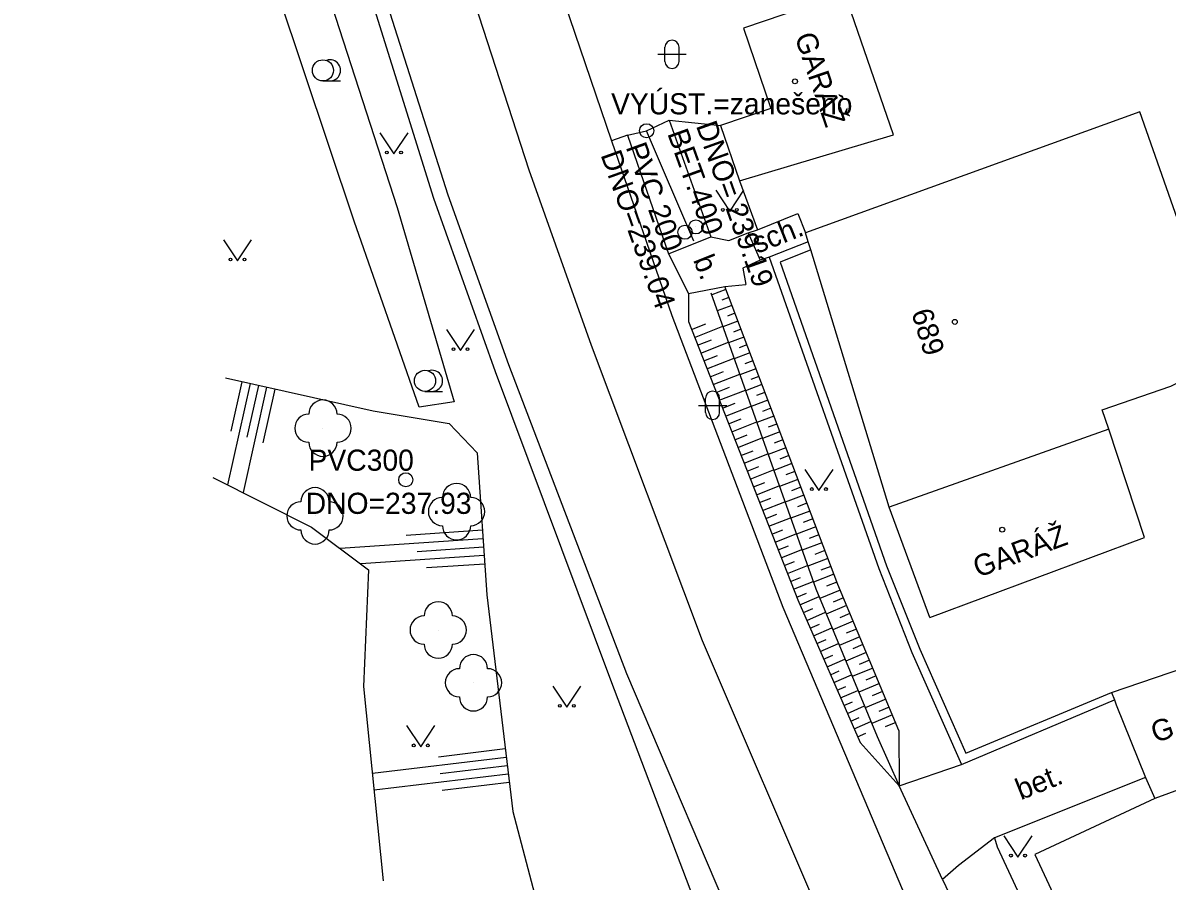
# Model space of a CAD drawing. Extents: x -621335 to -621199, y -1175437 to -1175180.
# Drawn here: x -621302.63 to -621262.05, y -1175367.71 to -1175337.27 of the extents above; entities that cross this region are included whole.
import ezdxf

# ---------------------------------------------------------------- set-up
doc = ezdxf.new("R2010")
doc.units = 0
for name, color, linetype in [('Budovy - měřené', 7, 'Continuous'), ('Budovy - zadní trakty', 7, 'Continuous'), ('Doplňkové značky', 7, 'Continuous'), ('Pomocné popisy', 7, 'Continuous'), ('Rozhraní ploch', 7, 'Continuous'), ('Výškopis', 7, 'Continuous'), ('Zeleň', 7, 'Continuous'), ('Značky druhů budov', 7, 'Continuous'), ('Značky kultur', 7, 'Continuous'), ('Čísla popisná_evidenční', 7, 'Continuous')]:
    doc.layers.add(name, color=color, linetype=linetype)

msp = doc.modelspace()

# ---------------------------------------------------------------- linework, layer by layer
at = {"layer": 'Budovy - měřené'}
msp.add_line((-621262.82, -1175364.04), (-621262.49, -1175364.79), dxfattribs=at)
for points in [[(-621277.08, -1175337.46), (-621276.1, -1175340.31), (-621277.89, -1175340.92), (-621277.22, -1175342.88)], [(-621270.47, -1175358.36), (-621271.91, -1175354.45), (-621274.69, -1175345.33), (-621274.78, -1175345.04), (-621274.88, -1175344.72)], [(-621264.02, -1175361.02), (-621263.92, -1175361.29), (-621263.86, -1175361.46)], [(-621262.49, -1175364.79), (-621266.74, -1175366.77), (-621264.62, -1175371.33)]]:
    msp.add_lwpolyline(points, dxfattribs=at)
at = {"layer": 'Budovy - zadní trakty'}
for points in [[(-621277.22, -1175342.88), (-621271.76, -1175341.24), (-621273.48, -1175336.23), (-621277.08, -1175337.46)], [(-621264.12, -1175351.69), (-621264.35, -1175351), (-621261.92, -1175350.16), (-621259.94, -1175349.19), (-621263.02, -1175340.43), (-621274.88, -1175344.72)], [(-621270.47, -1175358.36), (-621262.85, -1175355.53), (-621264.12, -1175351.69), (-621271.91, -1175354.45)], [(-621264.02, -1175361.02), (-621258.82, -1175359.25), (-621257.55, -1175362.98), (-621262.49, -1175364.79)]]:
    msp.add_lwpolyline(points, dxfattribs=at)
at = {"layer": 'Doplňkové značky'}
for p, q in [((-621277.22, -1175342.88), (-621276.58, -1175344.61)), ((-621275.15, -1175344.04), (-621274.88, -1175344.72)), ((-621276.91, -1175344.72), (-621276.48, -1175345.69)), ((-621263.86, -1175361.46), (-621262.82, -1175364.04))]:
    msp.add_line(p, q, dxfattribs=at)
for points in [[(-621277.59, -1175344.99), (-621276.91, -1175344.72), (-621276.58, -1175344.61), (-621275.15, -1175344.04)], [(-621274.78, -1175345.04), (-621276.16, -1175345.59), (-621272.28, -1175356.63), (-621271.1, -1175359.61), (-621269.34, -1175363.58), (-621263.92, -1175361.29)], [(-621274.69, -1175345.33), (-621275.78, -1175345.76), (-621272, -1175356.53), (-621270.82, -1175359.49), (-621269.19, -1175363.18), (-621264.02, -1175361.02)], [(-621276.16, -1175345.59), (-621276.48, -1175345.69), (-621277.1, -1175345.97), (-621276.99, -1175346.56)], [(-621262.82, -1175364.04), (-621268.17, -1175366.18), (-621269.45, -1175367.16)]]:
    msp.add_lwpolyline(points, dxfattribs=at)
for centre, radius in [((-621280.51, -1175341.1), 0.25), ((-621280.51, -1175341.1), 0.0005), ((-621279.15, -1175344.7), 0.25), ((-621278.76, -1175344.51), 0.25), ((-621278.76, -1175344.51), 0.0005), ((-621279.15, -1175344.7), 0.0005), ((-621289.051, -1175353.48), 0.25), ((-621289.051, -1175353.48), 0.0005)]:
    msp.add_circle(centre, radius, dxfattribs=at)
at = {"layer": 'Rozhraní ploch'}
for p, q in [((-621279.73, -1175345.47), (-621278.23, -1175344.86)), ((-621278.23, -1175344.86), (-621277.59, -1175344.99)), ((-621279.73, -1175345.47), (-621279.02, -1175346.87)), ((-621279.02, -1175346.87), (-621277.74, -1175346.63)), ((-621277.74, -1175346.63), (-621276.99, -1175346.56)), ((-621271.55, -1175364.33), (-621269.34, -1175363.58)), ((-621270.02, -1175367.66), (-621271.55, -1175364.33)), ((-621269.45, -1175367.16), (-621270.02, -1175367.66))]:
    msp.add_line(p, q, dxfattribs=at)
for points in [[(-621302.63, -1175296.18), (-621299, -1175307.51), (-621296.71, -1175314.71), (-621292.18, -1175328.86), (-621287.56, -1175343.37)], [(-621287.87, -1175322.58), (-621286.35, -1175327.4), (-621283.25, -1175337.09), (-621281.75, -1175341.46), (-621279.62, -1175347.65), (-621275.68, -1175358)], [(-621289.26, -1175328.38), (-621284.69, -1175342.49), (-621282.48, -1175348.71), (-621278.54, -1175359.18), (-621274.2, -1175369.3), (-621270.32, -1175376.95), (-621266.97, -1175382.2), (-621259.66, -1175391.26), (-621249.09, -1175401.63), (-621240, -1175407.99), (-621230.92, -1175409.11)], [(-621287.56, -1175343.37), (-621285.41, -1175349.39), (-621281.22, -1175360.35)], [(-621275.68, -1175358), (-621271.3, -1175368.33), (-621268.96, -1175373.16)], [(-621281.22, -1175360.35), (-621276.93, -1175370.43), (-621272.83, -1175378.46)]]:
    msp.add_lwpolyline(points, dxfattribs=at)
at = {"layer": 'Výškopis'}
for p, q in [((-621279.71, -1175340.73), (-621278.23, -1175344.86)), ((-621281.19, -1175341.26), (-621279.73, -1175345.47)), ((-621278.84, -1175345.02), (-621280.51, -1175341.1)), ((-621279.02, -1175346.87), (-621279.03, -1175347.87)), ((-621277.7, -1175346.735), (-621278.203, -1175346.926)), ((-621277.487, -1175347.296), (-621278.003, -1175347.491)), ((-621277.594, -1175347.015), (-621277.848, -1175347.112)), ((-621277.381, -1175347.576), (-621277.642, -1175347.675)), ((-621278.92, -1175348.149), (-621278.415, -1175347.951)), ((-621278.81, -1175348.428), (-621277.81, -1175348.035)), ((-621277.275, -1175347.857), (-621277.802, -1175348.057)), ((-621277.168, -1175348.137), (-621277.435, -1175348.239)), ((-621278.701, -1175348.708), (-621278.205, -1175348.513)), ((-621277.062, -1175348.418), (-621277.602, -1175348.623)), ((-621278.591, -1175348.987), (-621277.61, -1175348.601)), ((-621276.849, -1175348.979), (-621277.402, -1175349.188)), ((-621276.955, -1175348.698), (-621277.229, -1175348.802)), ((-621278.481, -1175349.266), (-621277.995, -1175349.075)), ((-621278.371, -1175349.545), (-621277.409, -1175349.167)), ((-621276.743, -1175349.259), (-621277.022, -1175349.365)), ((-621278.262, -1175349.824), (-621277.785, -1175349.637)), ((-621278.152, -1175350.104), (-621277.209, -1175349.733)), ((-621276.636, -1175349.54), (-621277.201, -1175349.754)), ((-621294.572, -1175350.066), (-621295.374, -1175353.659)), ((-621294.864, -1175350.001), (-621295.257, -1175351.761)), ((-621293.986, -1175350.197), (-621294.821, -1175353.937)), ((-621294.279, -1175350.131), (-621294.688, -1175351.965)), ((-621278.042, -1175350.383), (-621277.575, -1175350.199)), ((-621276.423, -1175350.101), (-621277.001, -1175350.32)), ((-621276.53, -1175349.82), (-621276.815, -1175349.929)), ((-621293.693, -1175350.262), (-621294.119, -1175352.169)), ((-621277.932, -1175350.662), (-621277.008, -1175350.299)), ((-621276.317, -1175350.381), (-621276.609, -1175350.492)), ((-621277.823, -1175350.941), (-621277.365, -1175350.761)), ((-621277.713, -1175351.22), (-621276.808, -1175350.865)), ((-621276.21, -1175350.662), (-621276.8, -1175350.885)), ((-621276.104, -1175350.942), (-621276.402, -1175351.055)), ((-621277.603, -1175351.5), (-621277.155, -1175351.324)), ((-621275.998, -1175351.223), (-621276.6, -1175351.451)), ((-621277.493, -1175351.779), (-621276.607, -1175351.43)), ((-621275.785, -1175351.784), (-621276.399, -1175352.017)), ((-621275.891, -1175351.503), (-621276.195, -1175351.619)), ((-621277.384, -1175352.058), (-621276.945, -1175351.886)), ((-621277.274, -1175352.337), (-621276.407, -1175351.996)), ((-621275.678, -1175352.064), (-621275.989, -1175352.182)), ((-621277.164, -1175352.616), (-621276.735, -1175352.448)), ((-621277.054, -1175352.896), (-621276.206, -1175352.562)), ((-621275.572, -1175352.345), (-621276.199, -1175352.582)), ((-621275.466, -1175352.625), (-621275.782, -1175352.745)), ((-621276.945, -1175353.175), (-621276.525, -1175353.01)), ((-621275.359, -1175352.906), (-621275.999, -1175353.148)), ((-621276.835, -1175353.454), (-621276.006, -1175353.128)), ((-621275.253, -1175353.186), (-621275.576, -1175353.309)), ((-621276.725, -1175353.733), (-621276.315, -1175353.572)), ((-621276.615, -1175354.012), (-621275.805, -1175353.694)), ((-621275.146, -1175353.467), (-621275.798, -1175353.714)), ((-621275.04, -1175353.747), (-621275.369, -1175353.872)), ((-621276.506, -1175354.292), (-621276.105, -1175354.134)), ((-621276.396, -1175354.571), (-621275.605, -1175354.26)), ((-621274.934, -1175354.028), (-621275.598, -1175354.28)), ((-621274.721, -1175354.589), (-621275.397, -1175354.845)), ((-621274.827, -1175354.308), (-621275.162, -1175354.435)), ((-621276.286, -1175354.85), (-621275.895, -1175354.696)), ((-621276.176, -1175355.129), (-621275.404, -1175354.826)), ((-621274.614, -1175354.869), (-621274.956, -1175354.999)), ((-621286.334, -1175355.273), (-621289.042, -1175355.456)), ((-621276.067, -1175355.408), (-621275.685, -1175355.259)), ((-621275.957, -1175355.688), (-621275.204, -1175355.392)), ((-621274.508, -1175355.15), (-621275.197, -1175355.411)), ((-621274.401, -1175355.43), (-621274.749, -1175355.562)), ((-621286.314, -1175355.573), (-621291.381, -1175355.914)), ((-621286.294, -1175355.872), (-621288.653, -1175356.031)), ((-621275.847, -1175355.967), (-621275.475, -1175355.821)), ((-621274.295, -1175355.711), (-621274.997, -1175355.977)), ((-621286.274, -1175356.171), (-621290.643, -1175356.466)), ((-621275.737, -1175356.246), (-621275.003, -1175355.958)), ((-621274.082, -1175356.272), (-621274.796, -1175356.542)), ((-621274.189, -1175355.991), (-621274.543, -1175356.125)), ((-621286.253, -1175356.471), (-621288.313, -1175356.609)), ((-621275.628, -1175356.525), (-621275.265, -1175356.383)), ((-621275.518, -1175356.804), (-621274.803, -1175356.523)), ((-621273.976, -1175356.552), (-621274.336, -1175356.689)), ((-621275.408, -1175357.084), (-621275.055, -1175356.945)), ((-621275.298, -1175357.363), (-621274.602, -1175357.089)), ((-621273.869, -1175356.832), (-621274.596, -1175357.108)), ((-621275.189, -1175357.642), (-621274.845, -1175357.507)), ((-621273.65, -1175357.391), (-621274.368, -1175357.692)), ((-621273.763, -1175357.113), (-621274.128, -1175357.252)), ((-621275.072, -1175357.918), (-621274.397, -1175357.623)), ((-621273.534, -1175357.667), (-621273.893, -1175357.818)), ((-621274.952, -1175358.193), (-621274.617, -1175358.047)), ((-621274.832, -1175358.468), (-621274.167, -1175358.178)), ((-621273.418, -1175357.944), (-621274.138, -1175358.246)), ((-621273.302, -1175358.221), (-621273.662, -1175358.372)), ((-621274.712, -1175358.743), (-621274.382, -1175358.599)), ((-621273.185, -1175358.497), (-621273.908, -1175358.801)), ((-621274.592, -1175359.018), (-621273.937, -1175358.732)), ((-621272.953, -1175359.051), (-621273.678, -1175359.355)), ((-621273.069, -1175358.774), (-621273.431, -1175358.926)), ((-621274.472, -1175359.293), (-621274.147, -1175359.151)), ((-621274.352, -1175359.568), (-621273.707, -1175359.286)), ((-621272.837, -1175359.327), (-621273.2, -1175359.48)), ((-621274.232, -1175359.843), (-621273.912, -1175359.703)), ((-621274.111, -1175360.118), (-621273.477, -1175359.841)), ((-621272.721, -1175359.604), (-621273.448, -1175359.909)), ((-621272.605, -1175359.88), (-621272.969, -1175360.033)), ((-621273.991, -1175360.393), (-621273.677, -1175360.255)), ((-621272.489, -1175360.157), (-621273.218, -1175360.463)), ((-621273.871, -1175360.668), (-621273.247, -1175360.395)), ((-621272.257, -1175360.71), (-621272.988, -1175361.017)), ((-621272.373, -1175360.434), (-621272.738, -1175360.587)), ((-621273.751, -1175360.943), (-621273.441, -1175360.807)), ((-621273.631, -1175361.218), (-621273.017, -1175360.949)), ((-621272.141, -1175360.987), (-621272.507, -1175361.141)), ((-621273.511, -1175361.492), (-621273.206, -1175361.359)), ((-621273.391, -1175361.767), (-621272.787, -1175361.503)), ((-621272.024, -1175361.264), (-621272.758, -1175361.572)), ((-621271.908, -1175361.54), (-621272.276, -1175361.694)), ((-621273.271, -1175362.042), (-621272.971, -1175361.911)), ((-621271.792, -1175361.817), (-621272.528, -1175362.126)), ((-621273.151, -1175362.317), (-621272.557, -1175362.058)), ((-621271.676, -1175362.093), (-621272.045, -1175362.248)), ((-621271.56, -1175362.37), (-621271.55, -1175364.33)), ((-621273.031, -1175362.592), (-621272.736, -1175362.464)), ((-621285.525, -1175363.029), (-621287.896, -1175363.313)), ((-621271.55, -1175364.33), (-621272.94, -1175362.8)), ((-621285.489, -1175363.327), (-621290.237, -1175363.895)), ((-621285.418, -1175363.923), (-621290.176, -1175364.493)), ((-621285.454, -1175363.625), (-621287.83, -1175363.909)), ((-621285.382, -1175364.22), (-621287.764, -1175364.506)), ((-621270.02, -1175367.66), (-621267.55, -1175372.72))]:
    msp.add_line(p, q, dxfattribs=at)
for points in [[(-621281.19, -1175341.26), (-621280.51, -1175341.1), (-621279.71, -1175340.73)], [(-621278.23, -1175346.85), (-621274.51, -1175357.35), (-621272.34, -1175362.58), (-621271.55, -1175364.33)], [(-621271.56, -1175362.37), (-621273.73, -1175357.2), (-621277.74, -1175346.63)], [(-621279.03, -1175347.87), (-621275.15, -1175357.74), (-621272.94, -1175362.8)], [(-621295.45, -1175349.87), (-621290.21, -1175351.04), (-621287.51, -1175351.48), (-621286.52, -1175352.52), (-621286.18, -1175357.56), (-621285.26, -1175365.24), (-621283.18, -1175373.16), (-621283.4, -1175378.38)], [(-621295.89, -1175353.4), (-621292.39, -1175355.16), (-621290.37, -1175356.67), (-621290.55, -1175360.81), (-621289.85, -1175367.7)], [(-621268.17, -1175366.18), (-621268.08, -1175366.5), (-621265.59, -1175371.86)]]:
    msp.add_lwpolyline(points, dxfattribs=at)
at = {"layer": 'Zeleň'}
for p, q in [((-621279.71, -1175340.73), (-621277.89, -1175340.92)), ((-621281.19, -1175341.26), (-621281.75, -1175341.46)), ((-621287.34, -1175350.72), (-621288.58, -1175350.91))]:
    msp.add_line(p, q, dxfattribs=at)
for points in [[(-621294.55, -1175327.79), (-621293.18, -1175327.93), (-621292.6, -1175329), (-621288.07, -1175343.49), (-621285.88, -1175349.64), (-621281.79, -1175360.58)], [(-621294.55, -1175327.79), (-621289.36, -1175343.82), (-621287.34, -1175350.72)], [(-621288.58, -1175350.91), (-621290.88, -1175344.31), (-621296.24, -1175328.3)], [(-621281.79, -1175360.58), (-621277.88, -1175370.89), (-621276.71, -1175376.23)]]:
    msp.add_lwpolyline(points, dxfattribs=at)
for centre in [(-621291.99, -1175351.65), (-621287.25, -1175354.61), (-621292.27, -1175354.76), (-621287.9, -1175358.81), (-621286.65, -1175360.68)]:
    msp.add_circle(centre, 0.0005, dxfattribs=at)
for centre, start, end in [((-621291.99, -1175351.15), 0, 180), ((-621292.49, -1175351.65), 90, 270), ((-621291.49, -1175351.65), 270, 90), ((-621291.99, -1175352.15), 180, 360), ((-621292.27, -1175354.26), 0, 180), ((-621287.25, -1175354.11), 0, 180), ((-621292.77, -1175354.76), 90, 270), ((-621291.77, -1175354.76), 270, 90), ((-621287.75, -1175354.61), 90, 270), ((-621286.75, -1175354.61), 270, 90), ((-621292.27, -1175355.26), 180, 360), ((-621287.25, -1175355.11), 180, 360), ((-621287.9, -1175358.31), 0, 180), ((-621288.4, -1175358.81), 90, 270), ((-621287.4, -1175358.81), 270, 90), ((-621287.9, -1175359.31), 180, 360), ((-621286.65, -1175360.18), 0, 180), ((-621287.15, -1175360.68), 90, 270), ((-621286.15, -1175360.68), 270, 90), ((-621286.65, -1175361.18), 180, 360)]:
    msp.add_arc(centre, 0.5, start, end, dxfattribs=at)
at = {"layer": 'Značky druhů budov'}
for centre in [(-621275.25, -1175339.35), (-621269.58, -1175347.88), (-621267.9, -1175355.25)]:
    msp.add_circle(centre, 0.0875, dxfattribs=at)
at = {"layer": 'Značky kultur'}
for p, q in [((-621280.11, -1175338.39), (-621279.11, -1175338.39)), ((-621279.86, -1175338.64), (-621279.86, -1175338.14)), ((-621279.36, -1175338.64), (-621279.36, -1175338.14)), ((-621291.99, -1175339.335), (-621291.365, -1175339.335)), ((-621288.37, -1175350.345), (-621287.745, -1175350.345)), ((-621278.42, -1175351.09), (-621278.42, -1175350.59)), ((-621277.92, -1175351.09), (-621277.92, -1175350.59)), ((-621278.67, -1175350.84), (-621277.67, -1175350.84))]:
    msp.add_line(p, q, dxfattribs=at)
for points in [[(-621289.97, -1175341.17), (-621289.47, -1175341.92), (-621288.97, -1175341.17)], [(-621278.06, -1175343.21), (-621277.56, -1175343.96), (-621277.06, -1175343.21)], [(-621295.52, -1175344.97), (-621295.02, -1175345.72), (-621294.52, -1175344.97)], [(-621287.61, -1175348.15), (-621287.11, -1175348.9), (-621286.61, -1175348.15)], [(-621274.9, -1175353.11), (-621274.4, -1175353.86), (-621273.9, -1175353.11)], [(-621283.84, -1175360.8), (-621283.34, -1175361.55), (-621282.84, -1175360.8)], [(-621289.02, -1175362.2), (-621288.52, -1175362.95), (-621288.02, -1175362.2)], [(-621267.84, -1175366.11), (-621267.34, -1175366.86), (-621266.84, -1175366.11)]]:
    msp.add_lwpolyline(points, dxfattribs=at)
for centre, radius in [((-621291.99, -1175338.96), 0.375), ((-621289.72, -1175341.87), 0.05), ((-621289.22, -1175341.87), 0.05), ((-621277.81, -1175343.91), 0.05), ((-621277.31, -1175343.91), 0.05), ((-621295.27, -1175345.67), 0.05), ((-621294.77, -1175345.67), 0.05), ((-621287.36, -1175348.85), 0.05), ((-621286.86, -1175348.85), 0.05), ((-621288.37, -1175349.97), 0.375), ((-621274.65, -1175353.81), 0.05), ((-621274.15, -1175353.81), 0.05), ((-621283.59, -1175361.5), 0.05), ((-621283.09, -1175361.5), 0.05), ((-621288.77, -1175362.9), 0.05), ((-621288.27, -1175362.9), 0.05), ((-621267.59, -1175366.81), 0.05), ((-621267.09, -1175366.81), 0.05)]:
    msp.add_circle(centre, radius, dxfattribs=at)
for centre, radius, start, end in [((-621279.61, -1175338.14), 0.25, 0, 180), ((-621291.74, -1175338.96), 0.375, 249.4944, 109.0474), ((-621279.61, -1175338.64), 0.25, 180, 360), ((-621288.12, -1175349.97), 0.375, 249.4944, 109.0474), ((-621278.17, -1175350.59), 0.25, 0, 180), ((-621278.17, -1175351.09), 0.25, 180, 360)]:
    msp.add_arc(centre, radius, start, end, dxfattribs=at)

# ---------------------------------------------------------------- texts
at = {"layer": 'Pomocné popisy'}
for s, rotation, p in [('GARÁŽ', 288.9381, (-621275.27, -1175337.76)), ('DNO= 239.19', 289.7153, (-621278.768, -1175340.918)), ('BET.400', 289.7153, (-621279.784, -1175341.195)), ('PVC 200', 289.7153, (-621281.259, -1175341.678)), ('DNO=239.04', 289.7153, (-621282.151, -1175341.954)), ('sch.', 21.7323, (-621276.59, -1175345.47)), ('b.', 291.73, (-621278.87, -1175345.68)), ('GARÁŽ', 20.3745, (-621268.76, -1175356.96)), ('GARÁŽ', 18.8305, (-621262.47, -1175362.82)), ('bet.', 21.8, (-621267.24, -1175364.85))]:
    msp.add_text(s, height=0.75, rotation=rotation, dxfattribs=at).set_placement(p)
for s, p in [('VYÚST.=zanešeno', (-621281.77, -1175340.52)), ('PVC300', (-621292.5, -1175353.16)), ('DNO=237.93', (-621292.6, -1175354.69))]:
    msp.add_text(s, height=0.75, dxfattribs=at).set_placement(p)
at = {"layer": 'Čísla popisná_evidenční'}
msp.add_text('689', height=0.75, rotation=286.96, dxfattribs=at).set_placement((-621271.13, -1175347.54))

doc.saveas('drawing.dxf')
